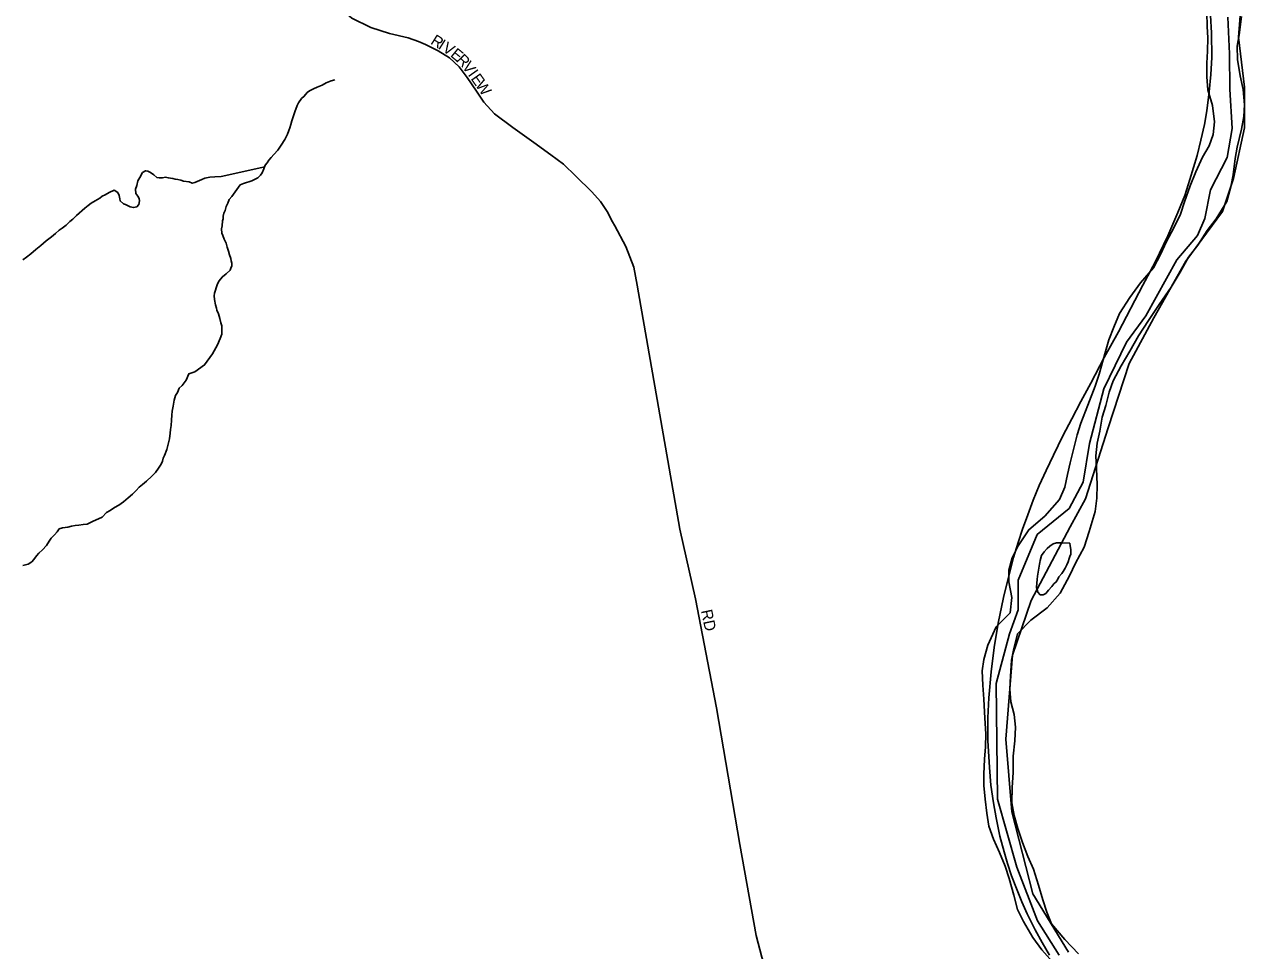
# Model space of a CAD drawing. Extents: x 2010165 to 2382125, y 1060529 to 1407316.
# Drawn here: x 2213739 to 2219146, y 1213095 to 1217199 of the extents above; entities that cross this region are included whole.
import ezdxf

# ---------------------------------------------------------------- set-up
doc = ezdxf.new("R2010")
doc.units = 0
for name, color, linetype in [('GM_X_Adjacent_County', 7, 'Continuous'), ('GM_X_City_Street', 7, 'Continuous'), ('GM_X_City_Street_Text', 7, 'Continuous'), ('GM_X_Corporation', 7, 'Continuous'), ('GM_X_County', 7, 'Continuous'), ('GM_X_Major_River', 7, 'Continuous'), ('GM_X_Minor_River', 7, 'Continuous'), ('GM_X_Rail_Line', 7, 'Continuous')]:
    doc.layers.add(name, color=color, linetype=linetype)

msp = doc.modelspace()

# ---------------------------------------------------------------- linework, layer by layer
at = {"layer": 'GM_X_Adjacent_County'}
msp.add_lwpolyline([(2218365.3, 1213088.4), (2218207.9, 1213346.9), (2218114.2, 1213710.3), (2218088, 1214032.6), (2218118, 1214403.5), (2218200.4, 1214647), (2218372.8, 1214973), (2218440.2, 1215096.6), (2218541.4, 1215411.3), (2218635, 1215696.1), (2218743.7, 1215898.4), (2218886.1, 1216149.4), (2219047.2, 1216370.4), (2219095.9, 1216516.6), (2219144.6, 1216741.4), (2219144.6, 1216921.2), (2219118.3, 1217142.2), (2219133.3, 1217333.3)], dxfattribs=at)
at = {"layer": 'GM_X_City_Street'}
for points in [[(2216345.4, 1216324.7), (2216321.7, 1216369.9), (2216291.4, 1216414), (2216253.2, 1216458), (2216181.8, 1216526.5), (2216128, 1216580.3), (2216072.2, 1216621.4), (2215996.9, 1216676.2), (2215902.9, 1216741.8), (2215822.7, 1216803.4), (2215774.7, 1216854.3), (2215742.4, 1216903.3), (2215701.3, 1216963.9), (2215666.1, 1217011.9), (2215623.1, 1217051), (2215572.2, 1217081.4), (2215516.4, 1217109.7), (2215485.1, 1217123.5), (2215439.1, 1217139.1), (2215356.9, 1217158.7), (2215274.7, 1217185.1), (2215190.5, 1217226.2), (2215169.5, 1217243.9)], [(2217838.9, 1211481.9), (2217548.9, 1211986.8), (2217291.5, 1212446.8), (2217228.9, 1212573), (2217127.1, 1212767.8), (2217033.2, 1212983), (2217006.8, 1213065.3), (2216981.3, 1213162.1), (2216908.9, 1213565.3), (2216805.2, 1214170.1), (2216713.2, 1214653.5), (2216643.7, 1214962.7), (2216454.9, 1216043.1), (2216439.2, 1216123.3), (2216404, 1216215.3), (2216355, 1216306.3), (2216345.4, 1216324.7)]]:
    msp.add_lwpolyline(points, dxfattribs=at)
at = {"layer": 'GM_X_Corporation'}
msp.add_lwpolyline([(2219071, 1217231.8), (2219078.5, 1217069.2), (2219079.9, 1216912.5), (2219091.4, 1216737.8), (2219068.9, 1216609.3), (2218994.3, 1216466.9), (2218969.8, 1216338.5), (2218937.5, 1216264.2), (2218844.9, 1216156), (2218707.7, 1215907.3), (2218623.1, 1215791), (2218522.1, 1215584.4), (2218459.2, 1215341.5), (2218430.6, 1215170.9), (2218368, 1215054.6), (2218227.3, 1214938.4), (2218142.4, 1214735.8), (2218142, 1214605.2), (2218103.5, 1214498.9), (2218044.7, 1214278.1), (2218051, 1213766.1), (2218136.3, 1213464.8), (2218227.8, 1213227.6), (2218323.6, 1213074.8)], dxfattribs=at)
at = {"layer": 'GM_X_County'}
msp.add_lwpolyline([(2219133.3, 1217333.3), (2219118.3, 1217142.2), (2219144.6, 1216921.2), (2219144.6, 1216741.4), (2219095.9, 1216516.6), (2219047.2, 1216370.4), (2218886.1, 1216149.4), (2218743.7, 1215898.4), (2218635, 1215696.1), (2218541.4, 1215411.3), (2218440.2, 1215096.6), (2218372.8, 1214973), (2218200.4, 1214647), (2218118, 1214403.5), (2218088, 1214032.6), (2218114.2, 1213710.3), (2218207.9, 1213346.9), (2218365.3, 1213088.4)], dxfattribs=at)
at = {"layer": 'GM_X_Major_River'}
for points in [[(2218978.1, 1217252.4), (2218980.6, 1217190.2), (2218983, 1217140.1), (2218981.6, 1217079.9), (2218978, 1217027.7), (2218978.5, 1216967.6), (2218983, 1216909.4), (2219003.7, 1216839.4), (2219012.3, 1216767.3), (2219006.8, 1216711), (2218989.2, 1216660.7), (2218959.6, 1216610.3), (2218930.1, 1216545.8), (2218904.7, 1216483.4), (2218879.3, 1216412.9), (2218861.7, 1216358.6), (2218834.2, 1216300.1), (2218798.8, 1216233.6), (2218775.2, 1216183.2), (2218741.7, 1216120.7), (2218684.2, 1216054), (2218636.7, 1215989.3), (2218591.3, 1215918.7), (2218565.8, 1215858.2), (2218544.3, 1215801.9), (2218528.7, 1215749.6), (2218501.6, 1215649), (2218484, 1215596.7), (2218450.7, 1215512.1), (2218419.4, 1215431.6), (2218403.8, 1215381.2), (2218390.3, 1215327), (2218372.9, 1215256.6), (2218361.3, 1215204.3), (2218349.8, 1215148), (2218326.3, 1215093.6), (2218260.9, 1215020.8), (2218189.3, 1214959.9), (2218141.9, 1214889.3), (2218116.4, 1214834.9), (2218100.8, 1214780.5), (2218101.3, 1214728.4), (2218113.9, 1214660.3), (2218106.5, 1214592), (2218045, 1214529.3), (2218007.6, 1214448.7), (2217990.2, 1214384.3), (2217982.6, 1214334.1), (2217985.2, 1214271.9), (2217989.7, 1214209.8), (2217994.4, 1214125.6), (2217999, 1214055.4), (2217997.5, 1213997.2), (2217994, 1213943), (2217990.6, 1213876.8), (2217991, 1213826.6), (2217995.5, 1213766.5), (2218004.1, 1213704.4), (2218012.6, 1213646.3), (2218033.1, 1213588.3), (2218059.7, 1213530.4), (2218084.2, 1213468.5), (2218102.7, 1213414.5), (2218123.4, 1213340.4), (2218139.9, 1213276.4), (2218166.4, 1213224.5), (2218207.1, 1213152.7)], [(2219132.3, 1217233.8), (2219121, 1217153.5), (2219113.5, 1217103.2), (2219114, 1217043.1), (2219126.6, 1216971), (2219139.1, 1216910.9), (2219145.7, 1216842.8), (2219142.2, 1216790.6), (2219132.7, 1216734.3), (2219113.3, 1216655.9), (2219103.8, 1216605.6), (2219094.4, 1216533.3), (2219084.8, 1216479.1), (2219067.4, 1216414.7), (2219020, 1216338), (2218980.4, 1216285.5), (2218939, 1216220.9), (2218897.4, 1216168.3), (2218859.9, 1216101.8), (2218820.5, 1216035.2), (2218767.1, 1215958.5), (2218719.7, 1215887.8), (2218676.2, 1215819.2), (2218636.8, 1215750.6), (2218599.3, 1215686), (2218563.9, 1215619.5), (2218546.3, 1215569.2), (2218530.8, 1215510.8), (2218515.3, 1215458.6), (2218503.8, 1215396.2), (2218492.2, 1215344), (2218486.7, 1215287.8), (2218489.2, 1215231.6), (2218491.8, 1215159.4), (2218490.4, 1215099.2), (2218482.9, 1215041), (2218457.6, 1214952.5), (2218434.2, 1214882), (2218396.8, 1214811.5), (2218369.2, 1214755), (2218327.9, 1214678.4), (2218270.4, 1214613.7), (2218198.8, 1214558.8), (2218139.3, 1214498.1), (2218123.8, 1214433.7), (2218112.3, 1214381.5), (2218108.9, 1214311.2), (2218105.4, 1214253), (2218109.9, 1214196.9), (2218124.4, 1214140.8), (2218130.9, 1214084.8), (2218127.4, 1214024.5), (2218120, 1213956.2), (2218120.6, 1213884), (2218115.2, 1213817.8), (2218113.8, 1213749.6), (2218124.3, 1213693.5), (2218140.8, 1213635.5), (2218161.4, 1213573.5), (2218185.9, 1213511.6), (2218210.4, 1213455.6), (2218233, 1213385.6), (2218251.6, 1213319.6), (2218270.1, 1213265.6), (2218290.6, 1213213.7), (2218349.2, 1213144), (2218409.8, 1213080.4)], [(2218330.8, 1214901.7), (2218370.9, 1214900.2), (2218373, 1214888.2), (2218375.3, 1214872.2), (2218375.5, 1214852.1), (2218371.6, 1214842), (2218367.8, 1214831.9), (2218363.9, 1214817.8), (2218358.1, 1214803.7), (2218350.3, 1214789.6), (2218342.4, 1214775.4), (2218336.6, 1214765.3), (2218322.7, 1214751.1), (2218318.9, 1214741), (2218311, 1214728.8), (2218301.1, 1214720.6), (2218291.2, 1214708.5), (2218277.4, 1214692.2), (2218265.6, 1214678), (2218253.6, 1214671.9), (2218239.6, 1214671.7), (2218229.4, 1214683.6), (2218223.2, 1214703.6), (2218224.9, 1214723.7), (2218226.7, 1214739.8), (2218228.5, 1214753.9), (2218237, 1214807.3)], [(2218330.8, 1214901.7), (2218370.9, 1214900.2), (2218373, 1214888.2), (2218375.3, 1214872.2), (2218375.5, 1214852.1), (2218371.6, 1214842), (2218367.8, 1214831.9), (2218363.9, 1214817.8), (2218358.1, 1214803.7), (2218350.3, 1214789.6), (2218342.4, 1214775.4), (2218336.6, 1214765.3), (2218322.7, 1214751.1), (2218318.9, 1214741), (2218311, 1214728.8), (2218301.1, 1214720.6), (2218291.2, 1214708.5), (2218277.4, 1214692.2), (2218265.6, 1214678), (2218253.6, 1214671.9), (2218239.6, 1214671.7), (2218229.4, 1214683.6), (2218223.2, 1214703.6), (2218224.9, 1214723.7), (2218226.7, 1214739.8), (2218228.5, 1214753.9), (2218237, 1214807.3)], [(2218237, 1214807.3), (2218237.8, 1214814.2), (2218239.6, 1214824.3), (2218245.3, 1214846.4), (2218257.2, 1214862.7), (2218271, 1214876.9), (2218282.9, 1214887.1), (2218296.8, 1214897.3), (2218312.8, 1214901.5), (2218324.8, 1214901.7), (2218330.8, 1214901.7)], [(2218237, 1214807.3), (2218237.8, 1214814.2), (2218239.6, 1214824.3), (2218245.3, 1214846.4), (2218257.2, 1214862.7), (2218271, 1214876.9), (2218282.9, 1214887.1), (2218296.8, 1214897.3), (2218312.8, 1214901.5), (2218324.8, 1214901.7), (2218330.8, 1214901.7)], [(2218207.1, 1213152.7), (2218247.5, 1213098.9), (2218306.2, 1213031.3)]]:
    msp.add_lwpolyline(points, dxfattribs=at)
at = {"layer": 'GM_X_Minor_River'}
for points in [[(2215114.2, 1216952.9), (2215098.2, 1216948.7), (2215076.3, 1216940.4), (2215058.4, 1216930.1), (2215036.4, 1216921.8), (2215020.5, 1216913.6), (2215002.6, 1216905.3), (2214992.7, 1216897.1), (2214978.9, 1216880.9), (2214967, 1216870.7), (2214953.2, 1216852.4), (2214947.3, 1216840.3), (2214937.7, 1216812.1), (2214929.9, 1216789.9), (2214924.2, 1216771.8), (2214920.4, 1216755.7), (2214914.5, 1216741.5), (2214910.7, 1216729.4), (2214904.9, 1216713.3), (2214893.2, 1216689.1), (2214877.5, 1216664.8), (2214861.7, 1216642.5), (2214844, 1216622.1), (2214832.1, 1216609.9), (2214822.2, 1216597.8), (2214814.4, 1216585.6), (2214806.5, 1216575.5), (2214800.7, 1216559.3), (2214792.9, 1216541.2), (2214785, 1216531), (2214773.2, 1216518.8), (2214747.3, 1216506.5), (2214709.4, 1216493.9), (2214695.4, 1216487.7), (2214658, 1216437.1), (2214646.2, 1216422.8), (2214640.4, 1216406.7), (2214632.6, 1216392.6), (2214628.8, 1216374.4), (2214622.9, 1216362.3), (2214619.1, 1216350.2), (2214619.2, 1216338.2), (2214617.4, 1216328.1), (2214615.7, 1216306), (2214611.8, 1216293.9), (2214614.1, 1216273.8), (2214618.2, 1216263.9), (2214624.4, 1216247.9), (2214632.7, 1216229.9), (2214636.9, 1216211.9), (2214643.2, 1216193.9), (2214647.4, 1216177.9), (2214653.6, 1216161.9), (2214655.7, 1216151.9), (2214657.9, 1216141.9), (2214658, 1216129.8), (2214654.1, 1216119.7), (2214650.3, 1216109.7), (2214632.5, 1216093.4), (2214616.6, 1216081.1), (2214600.8, 1216060.8), (2214593, 1216044.7), (2214581.5, 1216008.4), (2214579.6, 1215996.3), (2214581.8, 1215980.3), (2214586.2, 1215956.2), (2214590.3, 1215942.2), (2214592.5, 1215932.2), (2214598.7, 1215916.2), (2214605, 1215896.2), (2214609.2, 1215876.2), (2214613.4, 1215864.2), (2214613.9, 1215826.1), (2214606.1, 1215807.9), (2214594.5, 1215779.6), (2214572.9, 1215739.2), (2214537.5, 1215690.6), (2214493.8, 1215659.9), (2214467.9, 1215651.5), (2214456.2, 1215623.3), (2214438.5, 1215598.9), (2214424.7, 1215586.7), (2214416.9, 1215568.6), (2214409, 1215554.4), (2214403.3, 1215534.2), (2214397.6, 1215508.1), (2214393.9, 1215485.9), (2214392.1, 1215467.8), (2214390.4, 1215445.7), (2214388.7, 1215421.6), (2214387, 1215403.5), (2214385.2, 1215387.4), (2214381.5, 1215363.3), (2214375.8, 1215339.1), (2214370.1, 1215314.9), (2214360.4, 1215288.7), (2214354.6, 1215276.6), (2214350.7, 1215264.5), (2214344.9, 1215250.4), (2214333.1, 1215232.2), (2214319.3, 1215213.9)], [(2214804.1, 1216568.8), (2214610.8, 1216524.8), (2214582.8, 1216524.4), (2214560.7, 1216522.1), (2214538.8, 1216517.8), (2214524.8, 1216511.6), (2214514.9, 1216507.5), (2214494.9, 1216499.2), (2214483, 1216495.1), (2214468.9, 1216500.9), (2214444.8, 1216504.6), (2214432.7, 1216508.5), (2214418.6, 1216512.3), (2214406.6, 1216514.1), (2214396.5, 1216516), (2214376.4, 1216519.8), (2214364.4, 1216521.6), (2214350.4, 1216519.5), (2214336.4, 1216519.3), (2214326.3, 1216521.2), (2214312.1, 1216533), (2214298, 1216542.9), (2214285.9, 1216548.8), (2214275.9, 1216550.6), (2214261.9, 1216542.4), (2214250.2, 1216520.2), (2214242.4, 1216506), (2214236.6, 1216485.9), (2214230.8, 1216469.8), (2214233.1, 1216449.7), (2214241.3, 1216437.8), (2214247.4, 1216427.8), (2214249.5, 1216417.8), (2214245.7, 1216401.7), (2214237.8, 1216391.5), (2214221.9, 1216387.3), (2214207.8, 1216391.1), (2214187.6, 1216400.9), (2214177.6, 1216404.8), (2214163.4, 1216416.7), (2214161.3, 1216426.7), (2214159.1, 1216440.7), (2214152.9, 1216454.7), (2214136.7, 1216464.5), (2214114.8, 1216454.2), (2214096.9, 1216443.9), (2214083, 1216437.7), (2214073, 1216429.6), (2214053.2, 1216417.3), (2214035.3, 1216407), (2214021.4, 1216396.8), (2214007.5, 1216384.6), (2213969.9, 1216352), (2213954, 1216335.7), (2213940.2, 1216325.5), (2213924.3, 1216309.2), (2213906.5, 1216296.9), (2213892.6, 1216286.7), (2213876.7, 1216272.5), (2213858.9, 1216258.2), (2213835.1, 1216239.8), (2213811.3, 1216219.4), (2213789.5, 1216201.1), (2213767.7, 1216182.7), (2213747.8, 1216168.4), (2213732, 1216156.1)], [(2214319.3, 1215213.9), (2214303.5, 1215197.6), (2214279.7, 1215175.2), (2214261.9, 1215161), (2214248, 1215148.7), (2214234.2, 1215134.5), (2214218.4, 1215118.2), (2214198.6, 1215101.9), (2214178.7, 1215083.6), (2214156.9, 1215069.3), (2214139, 1215059), (2214119.1, 1215044.7), (2214103.2, 1215036.4), (2214083.4, 1215016.1), (2214053.6, 1215001.7), (2214043.6, 1214997.5), (2214017.7, 1214985.2), (2213999.7, 1214982.9), (2213979.7, 1214980.7), (2213963.7, 1214978.4), (2213947.7, 1214976.2), (2213931.7, 1214972), (2213907.8, 1214967.7), (2213893.8, 1214963.5), (2213883.9, 1214951.3), (2213872.1, 1214937.1), (2213858.2, 1214922.9), (2213848.4, 1214908.7), (2213836.6, 1214890.5), (2213818.9, 1214870.2), (2213803, 1214855.9), (2213793.2, 1214843.8), (2213781.3, 1214827.5), (2213771.5, 1214817.4), (2213755.6, 1214807.1), (2213731.6, 1214800.8)]]:
    msp.add_lwpolyline(points, dxfattribs=at)
at = {"layer": 'GM_X_Rail_Line'}
msp.add_lwpolyline([(2218280.8, 1213074.5), (2218248.3, 1213130.2), (2218217.3, 1213187), (2218182.7, 1213258.3), (2218159, 1213311.5), (2218135.7, 1213369.8), (2218113.5, 1213426.6), (2218095.5, 1213481.3), (2218080, 1213532.9), (2218061.4, 1213602.1), (2218044.3, 1213683.7), (2218033.5, 1213750.3), (2218021.6, 1213827.7), (2218014.9, 1213906.7), (2218008.2, 1214025.5), (2218008.2, 1214126.1), (2218012.8, 1214214.9), (2218022.1, 1214330.1), (2218036.6, 1214438.5), (2218053.1, 1214545.4), (2218077.9, 1214660), (2218106.8, 1214779.2), (2218121.8, 1214837.6), (2218142.4, 1214903.7), (2218162.1, 1214962.5), (2218184.8, 1215026.5), (2218209, 1215090.6), (2218235.9, 1215155.6), (2218266.3, 1215222.2), (2218298.3, 1215290.4), (2218340.2, 1215375.5), (2218379.9, 1215451.4), (2218420.7, 1215527.8), (2218465.1, 1215609.9), (2218524, 1215722.5), (2218586.4, 1215837.1), (2218695.4, 1216043.6), (2218749.1, 1216145.3), (2218805.3, 1216263), (2218850.2, 1216365.2), (2218880.2, 1216441.7), (2218903.4, 1216511.4), (2218935.4, 1216617.7), (2218952.5, 1216686.9), (2218967.4, 1216755), (2218977.8, 1216816.5), (2218989.1, 1216900.6), (2218996.4, 1216977), (2219000.5, 1217052.4), (2218999.5, 1217161.9), (2218994.3, 1217239.3)], dxfattribs=at)

# ---------------------------------------------------------------- texts
at = {"layer": 'GM_X_City_Street_Text'}
for s, rotation, p in [('R', 327.7449, (2215535.4, 1217115.3)), ('I', 327.7469, (2215568.9, 1217094.1)), ('V', 327.7467, (2215587.5, 1217082.4)), ('E', 320.8452, (2215623.4, 1217059.8)), ('R', 314.4848, (2215649.6, 1217038.6)), ('V', 306.6863, (2215676.2, 1217011.7)), ('I', 305.1819, (2215702.3, 1216976.7)), ('E', 305.1817, (2215715, 1216958.7)), ('W', 304.5761, (2215735.1, 1216930.1)), ('RD', 281.895, (2216736.5, 1214601.1))]:
    msp.add_text(s, height=50, rotation=rotation, dxfattribs=at).set_placement(p)

doc.saveas('drawing.dxf')
